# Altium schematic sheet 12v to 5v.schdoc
size 126 x 168 mm
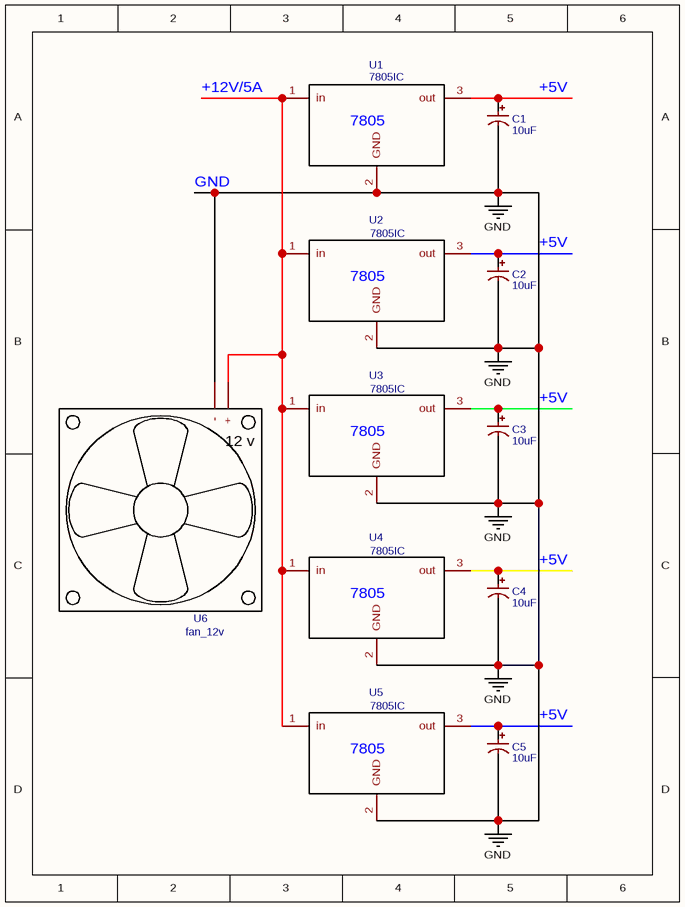
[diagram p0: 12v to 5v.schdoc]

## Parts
C1  10uF  [CAPACITOR1000UF16V]
C2  10uF  [CAPACITOR1000UF16V]
C3  10uF  [CAPACITOR1000UF16V]
C4  10uF  [CAPACITOR1000UF16V]
C5  10uF  [CAPACITOR1000UF16V]
U1  7805IC  [7805]
U2  7805IC  [7805]
U3  7805IC  [7805]
U4  7805IC  [7805]
U5  7805IC  [7805]
U6  fan_12v  [12V FAN]

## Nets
GND: C1.2(-) C2.2(-) C3.2(-) C4.2(-) C5.2(-) U1.2(GND) U2.2(GND) U3.2(GND) U4.2(GND) U5.2(GND) U6.2(-)
NetC1_1: C1.1(+) U1.3(out)
NetC2_1: C2.1(+) U2.3(out)
NetC3_1: C3.1(+) U3.3(out)
NetC4_1: C4.1(+) U4.3(out)
NetC5_1: C5.1(+) U5.3(out)
NetU1_1: U1.1(in) U2.1(in) U3.1(in) U4.1(in) U5.1(in) U6.1(+)

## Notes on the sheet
- +12V/5A
- (near C1) +5V
- GND
- (near C2) +5V
- (near C3) +5V
- (near C4) +5V
- (near C5) +5V

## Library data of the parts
C1-C5 = 10uF: BOM_Manufacturer: ValuePro; BOM_Manufacturer Part: electrolytic capacitor10UF50V; nameAlias: Capacitance
U1-U5 = 7805IC: Contributor: 53024
U6 = fan_12v: Contributor: ozgural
